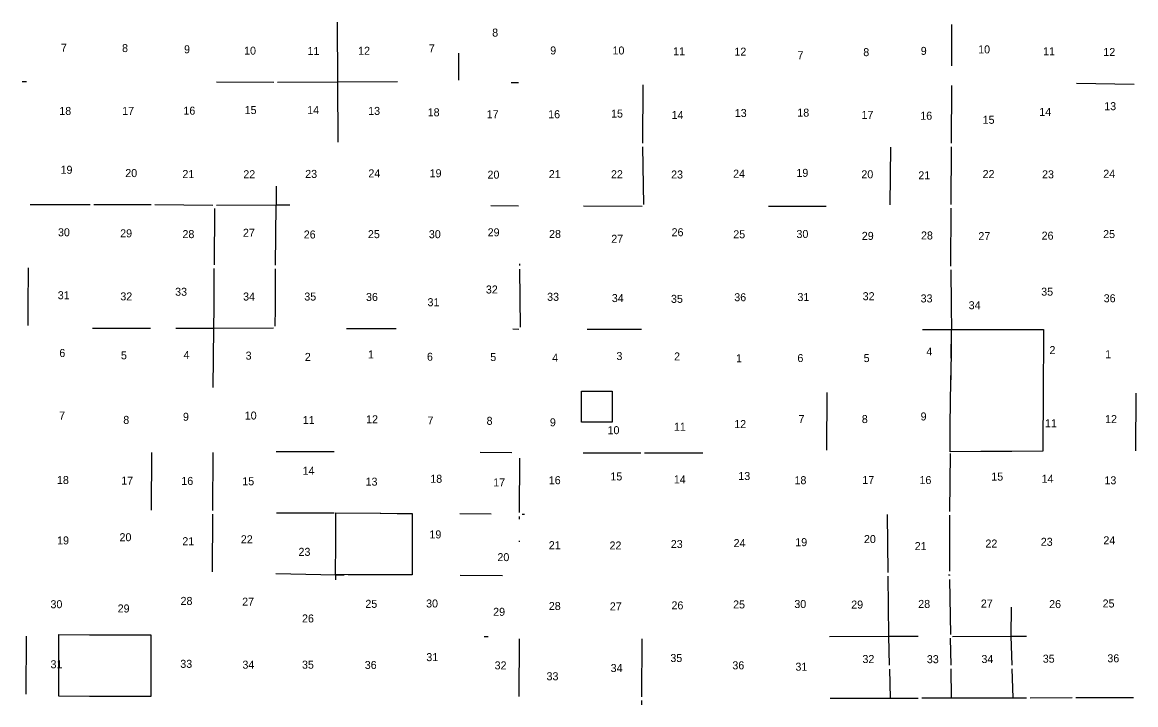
# Model space of a CAD drawing. Extents: x -2933025 to 31692252, y -2344676 to 23854604.
# Drawn here: x -2251611 to -2156079, y -2227156 to -2168601 of the extents above; entities that cross this region are included whole.
import ezdxf

# ---------------------------------------------------------------- set-up
doc = ezdxf.new("R2010")
doc.units = 0
for name, color, linetype in [('tdCoCorpBndry', 7, 'Continuous'), ('tdCoSectLinePart', 7, 'Continuous'), ('tdCoSectNmbr', 7, 'Continuous')]:
    doc.layers.add(name, color=color, linetype=linetype)

msp = doc.modelspace()

# ---------------------------------------------------------------- linework, layer by layer
at = {"layer": 'tdCoCorpBndry'}
for points in [[(-2166620, -2194962), (-2163981, -2194963), (-2163999, -2197523), (-2164008, -2198270), (-2164018, -2200095), (-2164059, -2205395), (-2166700, -2205416), (-2169364, -2205438), (-2172008, -2205455), (-2171994, -2204020), (-2171993, -2203976), (-2171993, -2203928), (-2171958, -2200430), (-2171954, -2200170), (-2171951, -2200029), (-2171916, -2198554), (-2171915, -2198509), (-2171914, -2198462), (-2171902, -2197879), (-2171895, -2197570), (-2171894, -2194957), (-2169237, -2194955)], [(-2203618, -2200261), (-2202881, -2200260), (-2202518, -2200258), (-2202146, -2200256), (-2201357, -2200258), (-2201013, -2200255), (-2200996, -2200255), (-2200999, -2202915), (-2203623, -2202909), (-2203623, -2201573), (-2203625, -2201220), (-2203622, -2200852), (-2203620, -2200487)], [(-2224697, -2210682), (-2220915, -2210724), (-2220868, -2210724), (-2220856, -2210725), (-2220845, -2210725), (-2219439, -2210750), (-2218153, -2210757), (-2218155, -2216014), (-2219448, -2216009), (-2223656, -2216003), (-2224729, -2215989), (-2224706, -2213306)], [(-2248462, -2221138), (-2245831, -2221150), (-2240571, -2221162), (-2240577, -2226444), (-2245099, -2226436), (-2245470, -2226436), (-2245841, -2226436), (-2248482, -2226418)]]:
    msp.add_lwpolyline(points, close=True, dxfattribs=at)
at = {"layer": 'tdCoSectLinePart'}
for points in [[(-2224581, -2168601), (-2224558, -2173703)], [(-2171852, -2172327), (-2171851, -2168779)], [(-2214144, -2173577), (-2214149, -2171245)], [(-2251611, -2173678), (-2251241, -2173676)], [(-2234949, -2173716), (-2230034, -2173737)], [(-2229718, -2173737), (-2224558, -2173703)], [(-2224558, -2173703), (-2219420, -2173689)], [(-2224558, -2173703), (-2224545, -2178881)], [(-2209663, -2173771), (-2209050, -2173776)], [(-2198381, -2178960), (-2198353, -2173982)], [(-2171880, -2178984), (-2171854, -2174024)], [(-2161150, -2173813), (-2156206, -2173915)], [(-2198296, -2184239), (-2198379, -2179278)], [(-2177127, -2179303), (-2177180, -2184251)], [(-2171902, -2184245), (-2171881, -2179300)], [(-2229822, -2182661), (-2229830, -2184263)], [(-2250933, -2184237), (-2245798, -2184229)], [(-2245481, -2184229), (-2240557, -2184244)], [(-2240240, -2184246), (-2235263, -2184285)], [(-2235106, -2184591), (-2235139, -2189412)], [(-2234946, -2184286), (-2229830, -2184263)], [(-2229874, -2189433), (-2229830, -2184263)], [(-2229830, -2184263), (-2228661, -2184279)], [(-2211397, -2184329), (-2209047, -2184343)], [(-2203472, -2184351), (-2198438, -2184380)], [(-2187579, -2184393), (-2182651, -2184383)], [(-2171932, -2189516), (-2171904, -2184562)], [(-2208912, -2189477), (-2208911, -2189314)], [(-2251102, -2194631), (-2251100, -2193122), (-2251098, -2193037), (-2251088, -2189673)], [(-2235184, -2194846), (-2235137, -2193089), (-2235136, -2193018), (-2235136, -2192910), (-2235140, -2189729)], [(-2229908, -2194684), (-2229888, -2193119), (-2229891, -2193007), (-2229876, -2189750)], [(-2208874, -2194770), (-2208911, -2189794)], [(-2171932, -2189832), (-2171912, -2192851), (-2171911, -2193016), (-2171896, -2194952)], [(-2245576, -2194834), (-2240612, -2194843)], [(-2238436, -2194845), (-2235184, -2194846)], [(-2235229, -2199926), (-2235184, -2194846)], [(-2235184, -2194846), (-2230057, -2194831)], [(-2223790, -2194868), (-2219535, -2194863)], [(-2209514, -2194917), (-2209012, -2194919)], [(-2203135, -2194926), (-2198488, -2194944)], [(-2174369, -2194956), (-2171896, -2194952)], [(-2171924, -2197412), (-2171896, -2194952)], [(-2171896, -2194952), (-2169805, -2194956)], [(-2171954, -2200011), (-2171928, -2197725)], [(-2182569, -2200361), (-2182597, -2205305)], [(-2156079, -2200425), (-2156095, -2205384)], [(-2240511, -2210471), (-2240498, -2205513)], [(-2235261, -2210477), (-2235235, -2205523)], [(-2229817, -2205426), (-2224863, -2205434)], [(-2212325, -2205499), (-2209622, -2205522)], [(-2203476, -2205542), (-2198539, -2205544)], [(-2198222, -2205544), (-2193228, -2205532)], [(-2172011, -2205610), (-2172055, -2210582)], [(-2208951, -2210668), (-2208929, -2205999)], [(-2235279, -2215740), (-2235262, -2210794)], [(-2229805, -2210705), (-2224859, -2210683)], [(-2214060, -2210762), (-2211367, -2210780)], [(-2208950, -2211241), (-2208951, -2211013)], [(-2208708, -2210798), (-2208518, -2210799)], [(-2177414, -2210839), (-2177351, -2215804)], [(-2172056, -2210901), (-2172058, -2215684)], [(-2208946, -2213189), (-2208947, -2213094)], [(-2229842, -2215904), (-2224708, -2216001)], [(-2224710, -2216445), (-2224708, -2216001)], [(-2224708, -2216001), (-2224708, -2215990)], [(-2224708, -2216001), (-2223999, -2216002)], [(-2214048, -2216032), (-2210418, -2216063)], [(-2177347, -2216121), (-2177279, -2221268)], [(-2172148, -2216013), (-2172059, -2216014)], [(-2172059, -2216011), (-2172059, -2216014)], [(-2172059, -2216014), (-2172050, -2216014)], [(-2172059, -2216014), (-2172058, -2216063)], [(-2172051, -2216401), (-2171964, -2221132)], [(-2166758, -2218774), (-2166785, -2221268)], [(-2251276, -2221287), (-2251309, -2226236)], [(-2211972, -2221309), (-2211631, -2221311)], [(-2208971, -2226441), (-2208964, -2221492)], [(-2198441, -2226467), (-2198435, -2221504)], [(-2182366, -2221295), (-2177279, -2221268)], [(-2177279, -2221268), (-2174753, -2221279)], [(-2177279, -2221268), (-2177224, -2223775)], [(-2171927, -2223773), (-2171959, -2221448)], [(-2171802, -2221290), (-2166785, -2221268)], [(-2166785, -2221268), (-2165458, -2221271)], [(-2166785, -2221268), (-2166709, -2223762)], [(-2177217, -2224093), (-2177162, -2226585)], [(-2171888, -2226573), (-2171922, -2224088)], [(-2166699, -2224080), (-2166623, -2226570)], [(-2198441, -2227156), (-2198441, -2226784)], [(-2182295, -2226590), (-2177162, -2226585)], [(-2177162, -2226585), (-2174755, -2226579)], [(-2177162, -2226585), (-2177162, -2226587)], [(-2174438, -2226578), (-2171957, -2226573)], [(-2171957, -2226573), (-2166623, -2226570), (-2165458, -2226564)], [(-2165137, -2226563), (-2161541, -2226545)], [(-2161224, -2226545), (-2156266, -2226545)]]:
    msp.add_lwpolyline(points, dxfattribs=at)

# ---------------------------------------------------------------- texts
at = {"layer": 'tdCoSectNmbr'}
for s, height, rotation, p in [('8', 686, 0.00627, (-2211293, -2169829)), ('7', 686, 0.00086, (-2248293, -2171124)), ('8', 686, 0.00167, (-2243050, -2171159)), ('9', 686, 0.00242, (-2237731, -2171261)), ('10', 686.4, 0.00319, (-2232580, -2171383)), ('11', 686.4, 0.00396, (-2227138, -2171407)), ('12', 686.4, 0.00461, (-2222795, -2171389)), ('7', 686, 0.00548, (-2216727, -2171184)), ('9', 686, 0.00699, (-2206314, -2171362)), ('10', 686.4, 0.00777, (-2200969, -2171365)), ('11', 686.4, 0.00849, (-2195769, -2171434)), ('12', 686.4, 0.00924, (-2190512, -2171461)), ('7', 686, 0.00996, (-2185100, -2171769)), ('8', 686, 0.01249, (-2179454, -2171509)), ('9', 686, 0.0132, (-2174523, -2171398)), ('10', 686.4, 0.01393, (-2169598, -2171272)), ('11', 686.4, 0.01473, (-2164025, -2171433)), ('12', 686.4, 0.01548, (-2158858, -2171497)), ('18', 686.4, 0.00083, (-2248433, -2176551)), ('17', 686.4, 0.00165, (-2243038, -2176552)), ('16', 686.4, 0.0024, (-2237787, -2176530)), ('15', 686.4, 0.00317, (-2232535, -2176476)), ('14', 686.4, 0.00394, (-2227166, -2176479)), ('13', 686.4, 0.0047, (-2221934, -2176550)), ('18', 686.4, 0.00544, (-2216827, -2176669)), ('17', 686.4, 0.00619, (-2211764, -2176835)), ('16', 686.4, 0.00696, (-2206490, -2176836)), ('15', 686.4, 0.00774, (-2201093, -2176779)), ('14', 686.4, 0.00849, (-2195904, -2176903)), ('13', 686.4, 0.00928, (-2190481, -2176730)), ('18', 686.4, 0.01002, (-2185114, -2176697)), ('17', 686.4, 0.01237, (-2179608, -2176892)), ('14', 686.4, 0.01458, (-2164353, -2176633)), ('13', 686.4, 0.0154, (-2158781, -2176144)), ('16', 686.4, 0.0131, (-2174565, -2176962)), ('15', 686.4, 0.01386, (-2169211, -2177313)), ('19', 686.4, 0.00087, (-2248327, -2181600)), ('20', 686.4, 0.00165, (-2242774, -2181883)), ('21', 686.4, 0.0024, (-2237872, -2181967)), ('22', 686.4, 0.00315, (-2232647, -2181983)), ('23', 686.4, 0.00392, (-2227335, -2181955)), ('24', 686.4, 0.0047, (-2221915, -2181910)), ('19', 686.4, 0.00548, (-2216661, -2181898)), ('20', 686.4, 0.0062, (-2211696, -2182017)), ('21', 686.4, 0.00694, (-2206435, -2181972)), ('22', 686.4, 0.00773, (-2201101, -2181981)), ('23', 686.4, 0.00854, (-2195944, -2182004)), ('24', 686.4, 0.00925, (-2190622, -2181938)), ('19', 686.4, 0.01003, (-2185192, -2181865)), ('20', 686.4, 0.01231, (-2179619, -2181987)), ('21', 686.4, 0.01295, (-2174730, -2182076)), ('22', 686.4, 0.01377, (-2169215, -2181968)), ('23', 686.4, 0.01452, (-2164117, -2181992)), ('24', 686.4, 0.01528, (-2158863, -2181946)), ('30', 686.4, 0.0008, (-2248548, -2186963)), ('29', 686.4, 0.00159, (-2243210, -2187051)), ('28', 686.4, 0.00238, (-2237867, -2187121)), ('27', 686.4, 0.00315, (-2232677, -2187005)), ('26', 686.4, 0.00388, (-2227462, -2187153)), ('25', 686.4, 0.00469, (-2221955, -2187124)), ('30', 686.4, 0.00545, (-2216727, -2187129)), ('29', 686.4, 0.00618, (-2211682, -2186966)), ('28', 686.4, 0.00691, (-2206414, -2187107)), ('26', 686.4, 0.00847, (-2195900, -2186959)), ('25', 686.4, 0.00924, (-2190610, -2187135)), ('30', 686.4, 0.01001, (-2185188, -2187110)), ('29', 686.4, 0.01217, (-2179581, -2187273)), ('28', 686.4, 0.01287, (-2174502, -2187237)), ('27', 686.4, 0.01361, (-2169582, -2187295)), ('26', 686.4, 0.0144, (-2164154, -2187253)), ('25', 686.4, 0.01517, (-2158875, -2187118)), ('27', 686.4, 0.00774, (-2201076, -2187522)), ('33', 686.4, 0.00235, (-2238497, -2192066)), ('32', 686.4, 0.00616, (-2211834, -2191871)), ('35', 686.4, 0.0143, (-2164190, -2192058)), ('31', 686.4, 0.00081, (-2248566, -2192363)), ('32', 686.4, 0.00158, (-2243198, -2192463)), ('34', 686.4, 0.00313, (-2232664, -2192475)), ('35', 686.4, 0.00386, (-2227413, -2192477)), ('36', 686.4, 0.00467, (-2222121, -2192514)), ('31', 686.4, 0.00538, (-2216841, -2192962)), ('33', 686.4, 0.00692, (-2206581, -2192499)), ('34', 686.4, 0.00771, (-2201028, -2192608)), ('35', 686.4, 0.00845, (-2195953, -2192676)), ('36', 686.4, 0.00923, (-2190523, -2192536)), ('31', 686.4, 0.00998, (-2185104, -2192518)), ('32', 686.4, 0.01207, (-2179506, -2192447)), ('33', 686.4, 0.0128, (-2174535, -2192638)), ('36', 686.4, 0.01507, (-2158827, -2192624)), ('34', 686.4, 0.01338, (-2170414, -2193223)), ('6', 686, 0.00082, (-2248431, -2197319)), ('5', 686, 0.00159, (-2243144, -2197518)), ('4', 686, 0.0023, (-2237773, -2197482)), ('3', 686, 0.00316, (-2232448, -2197544)), ('2', 686, 0.00386, (-2227368, -2197656)), ('1', 686, 0.00463, (-2221947, -2197444)), ('6', 686, 0.00538, (-2216891, -2197640)), ('5', 686, 0.00616, (-2211458, -2197667)), ('4', 686, 0.00693, (-2206145, -2197722)), ('3', 686, 0.00773, (-2200633, -2197577)), ('2', 686, 0.00845, (-2195686, -2197615)), ('1', 686, 0.00921, (-2190372, -2197772)), ('6', 686, 0.00998, (-2185106, -2197753)), ('5', 686, 0.01197, (-2179421, -2197756)), ('4', 686, 0.01276, (-2174043, -2197192)), ('2', 686, 0.01429, (-2163477, -2197070)), ('1', 686, 0.01496, (-2158701, -2197426)), ('7', 686, 0.00076, (-2248449, -2202689)), ('10', 686.4, 0.0031, (-2232523, -2202685)), ('8', 686, 0.00156, (-2242945, -2203059)), ('9', 686, 0.00229, (-2237823, -2202790)), ('11', 686.4, 0.00383, (-2227544, -2203072)), ('12', 686.4, 0.00459, (-2222109, -2203008)), ('7', 686, 0.00536, (-2216842, -2203112)), ('8', 686, 0.00609, (-2211774, -2203140)), ('9', 686, 0.00687, (-2206343, -2203268)), ('11', 686.4, 0.00842, (-2195704, -2203648)), ('12', 686.4, 0.00918, (-2190526, -2203418)), ('7', 686, 0.01012, (-2185010, -2202984)), ('8', 686, 0.01186, (-2179579, -2202990)), ('9', 686, 0.01259, (-2174536, -2202762)), ('11', 686.4, 0.01423, (-2163869, -2203353)), ('12', 686.4, 0.01486, (-2158709, -2202988)), ('10', 686.4, 0.00774, (-2201396, -2203942)), ('14', 686.4, 0.00378, (-2227559, -2207424)), ('18', 686.4, 0.00074, (-2248634, -2208219)), ('17', 686.4, 0.00154, (-2243123, -2208275)), ('16', 686.4, 0.00224, (-2237965, -2208296)), ('15', 686.4, 0.00303, (-2232732, -2208322)), ('13', 686.4, 0.00456, (-2222155, -2208360)), ('18', 686.4, 0.00528, (-2216606, -2208113)), ('17', 686.4, 0.00616, (-2211207, -2208427)), ('16', 686.4, 0.00685, (-2206439, -2208234)), ('15', 686.4, 0.0076, (-2201151, -2207911)), ('14', 686.4, 0.00838, (-2195709, -2208165)), ('13', 686.4, 0.0092, (-2190177, -2207875)), ('18', 686.4, 0.00988, (-2185356, -2208234)), ('17', 686.4, 0.01179, (-2179535, -2208216)), ('16', 686.4, 0.0125, (-2174632, -2208221)), ('15', 686.4, 0.0133, (-2168471, -2207928)), ('14', 686.4, 0.014, (-2164155, -2208117)), ('13', 686.4, 0.01478, (-2158765, -2208242)), ('20', 686.4, 0.00148, (-2243268, -2213127)), ('19', 686.4, 0.00529, (-2216677, -2212886)), ('19', 686.4, 0.00071, (-2248625, -2213400)), ('21', 686.4, 0.00226, (-2237878, -2213467)), ('22', 686.4, 0.00304, (-2232859, -2213303)), ('21', 686.4, 0.00682, (-2206437, -2213810)), ('22', 686.4, 0.0076, (-2201225, -2213833)), ('23', 686.4, 0.00835, (-2195970, -2213711)), ('24', 686.4, 0.00912, (-2190580, -2213630)), ('19', 686.4, 0.00988, (-2185290, -2213551)), ('20', 686.4, 0.01173, (-2179397, -2213284)), ('21', 686.4, 0.01234, (-2175042, -2213888)), ('22', 686.4, 0.01323, (-2168974, -2213668)), ('23', 686.4, 0.01391, (-2164226, -2213521)), ('24', 686.4, 0.01471, (-2158857, -2213393)), ('23', 686.4, 0.00379, (-2227911, -2214381)), ('20', 686.4, 0.00619, (-2210845, -2214837)), ('30', 686.4, 0.00068, (-2249192, -2218876)), ('28', 686.4, 0.00223, (-2238031, -2218591)), ('27', 686.4, 0.00301, (-2232743, -2218653)), ('25', 686.4, 0.00452, (-2222174, -2218842)), ('30', 686.4, 0.00528, (-2216964, -2218812)), ('25', 686.4, 0.00909, (-2190623, -2218894)), ('30', 686.4, 0.00985, (-2185371, -2218858)), ('29', 686.4, 0.01144, (-2180490, -2218905)), ('28', 686.4, 0.01228, (-2174741, -2218850)), ('27', 686.4, 0.01308, (-2169366, -2218816)), ('26', 686.4, 0.0139, (-2163508, -2218863)), ('25', 686.4, 0.01459, (-2158919, -2218813)), ('29', 686.4, 0.00148, (-2243427, -2219240)), ('29', 686.4, 0.00611, (-2211210, -2219525)), ('28', 686.4, 0.0068, (-2206434, -2219027)), ('27', 686.4, 0.00753, (-2201200, -2219061)), ('26', 686.4, 0.00832, (-2195911, -2218973)), ('26', 686.4, 0.00374, (-2227610, -2220097)), ('31', 686.4, 0.00527, (-2216945, -2223414)), ('35', 686.4, 0.00827, (-2196006, -2223489)), ('32', 686.4, 0.01153, (-2179527, -2223580)), ('33', 686.4, 0.01233, (-2174002, -2223591)), ('34', 686.4, 0.01299, (-2169317, -2223576)), ('35', 686.4, 0.01376, (-2164056, -2223548)), ('36', 686.4, 0.01456, (-2158513, -2223514)), ('31', 686.4, 0.00056, (-2249186, -2224027)), ('33', 686.4, 0.0022, (-2238054, -2223990)), ('34', 686.4, 0.00298, (-2232722, -2224061)), ('35', 686.4, 0.00371, (-2227611, -2224063)), ('36', 686.4, 0.00449, (-2222227, -2224087)), ('32', 686.4, 0.00608, (-2211085, -2224124)), ('34', 686.4, 0.00752, (-2201130, -2224351)), ('36', 686.4, 0.00905, (-2190687, -2224118)), ('31', 686.4, 0.00981, (-2185276, -2224237)), ('33', 686.4, 0.00676, (-2206630, -2225055))]:
    msp.add_text(s, height=height, rotation=rotation, dxfattribs=at).set_placement(p)

doc.saveas('drawing.dxf')
